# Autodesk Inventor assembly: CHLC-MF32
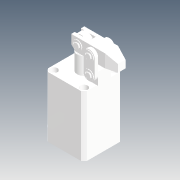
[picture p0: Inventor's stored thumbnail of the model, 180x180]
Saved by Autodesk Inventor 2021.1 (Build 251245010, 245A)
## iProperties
Company: Microsoft
Created: 2019-11
Part Number: CHLC-MF32
Description: STEP AP214
Document SubType Name: Assembly
Designer: user
Title: CHLC-MF32.STEP
Author: Windows
Revision Number: ÈÎºÎ
Sending System: SolidWorks 2015
Preprocessor: SwSTEP 2.0
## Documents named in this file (13)
- D:\Vault_2016\Projekty\Clamptek\Hydraulic\CHLC\CHLC-32\Inventor\CHLC-MF32\CHLC-MF32.iam
- D:\Vault_2016\Projekty\Clamptek\Hydraulic\CHLC\CHLC-32\Inventor\CHLC-MF32\CHLC-MF32-01.ipt
- D:\Vault_2016\Projekty\Clamptek\Hydraulic\CHLC\CHLC-32\Inventor\CHLC-MF32\CHLC-MF32-02.ipt
- D:\Vault_2016\Projekty\Clamptek\Hydraulic\CHLC\CHLC-32\Inventor\CHLC-MF32\CHLC-32-08.ipt
- D:\Vault_2016\Projekty\Clamptek\Hydraulic\CHLC\CHLC-32\Inventor\CHLC-MF32\CHLC-32-03.ipt
- D:\Vault_2016\Projekty\Clamptek\Hydraulic\CHLC\CHLC-32\Inventor\CHLC-MF32\CHLC-32-02.ipt
- D:\Vault_2016\Projekty\Clamptek\Hydraulic\CHLC\CHLC-32\Inventor\CHLC-MF32\CHLC-32-04.ipt
- D:\Vault_2016\Projekty\Clamptek\Hydraulic\CHLC\CHLC-32\Inventor\CHLC-MF32\TXF_ASM.iam
- D:\Vault_2016\Projekty\Clamptek\Hydraulic\CHLC\CHLC-32\Inventor\CHLC-MF32\M6.ipt
- D:\Vault_2016\Projekty\Clamptek\Hydraulic\CHLC\CHLC-32\Inventor\CHLC-MF32\LHC01D-40-08.ipt
- D:\Vault_2016\Projekty\Clamptek\Hydraulic\CHLC\CHLC-32\Inventor\CHLC-MF32\M6LS.ipt
- D:\Vault_2016\Projekty\Clamptek\Hydraulic\CHLC\CHLC-32\Inventor\CHLC-MF32\M6LC.ipt
- D:\Vault_2016\Projekty\Clamptek\Hydraulic\CHLC\CHLC-32\Inventor\CHLC-MF32\Ñ¹±Û.ipt
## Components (20 placed, 20 different names)
1. CHLC-MF32-01_1
2. CHLC-MF32-02_2
3. CHLC-32-08_3
4. CHLC-32-03_4
5. CHLC-32-03_5
6. CHLC-32-02_6
7. CHLC-32-04_7
8. CHLC-32-04_8
9. TXF_ASM_9 [sub-assembly]
10. M6_10
11. LHC01D-40-08_11
12. LHC01D-40-08_12
13. LHC01D-40-08_13
14. LHC01D-40-08_14
15. LHC01D-40-08_15
16. LHC01D-40-08_16
17. M6LS_17
18. M6LC_18
19. M6LC_19
20. Ñ¹±Û_20
